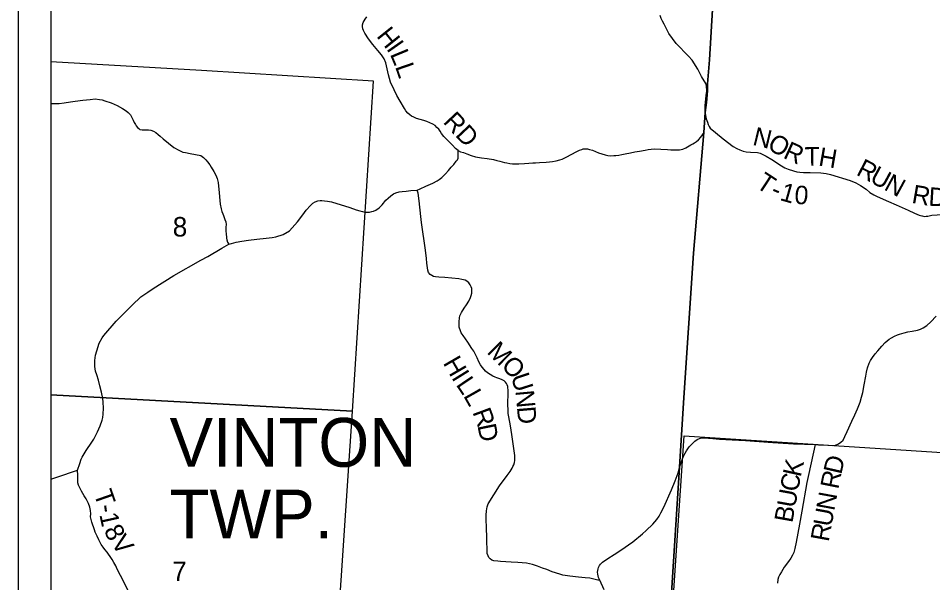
# Model space of a CAD drawing. Extents: x 0 to 34, y 0 to 22.
# Drawn here: x 2 to 4.807, y 15.408 to 17.141 of the extents above; entities that cross this region are included whole.
import ezdxf

# ---------------------------------------------------------------- set-up
doc = ezdxf.new("R2010")
doc.units = 0
for name, color, linetype in [('GM_X_Corporation', 7, 'Continuous'), ('GM_X_County_Road', 7, 'Continuous'), ('GM_X_County_Road_Text', 7, 'Continuous'), ('GM_X_Section_Text', 7, 'Continuous'), ('GM_X_State_Route', 7, 'Continuous'), ('GM_X_Township_Road', 7, 'Continuous'), ('GM_X_Township_Road_Text', 7, 'Continuous'), ('GM_X_Township_Text', 7, 'Continuous'), ('SH_Data', 7, 'Continuous')]:
    doc.layers.add(name, color=color, linetype=linetype)

msp = doc.modelspace()

# ---------------------------------------------------------------- linework, layer by layer
at = {"layer": 'GM_X_Corporation'}
msp.add_lwpolyline([(2.1, 20.9), (2.1, 14.9497), (2.4519, 14.9275), (2.9562, 14.8958), (3.5107, 14.8614), (3.9742, 14.8327), (4.0069, 15.4088), (4.03, 15.7625), (4.0425, 15.9604), (4.0732, 16.4197), (4.1048, 16.7908), (4.1087, 16.8515), (4.1128, 16.8828), (4.1159, 16.9184), (4.1162, 16.9397), (4.1215, 17.0136), (4.1603, 17.6679)], dxfattribs=at)
for points in [[(2.1, 17.0076), (2.1, 15.9854), (3.0263, 15.9353), (3.0901, 16.9477), (2.5628, 16.9805)], [(2.1, 15.9854), (2.1, 14.9539), (2.9567, 14.8961), (3.0263, 15.9353)], [(4.0444, 15.8589), (5.0732, 15.7926), (5.0032, 14.775), (3.9752, 14.8336)]]:
    msp.add_lwpolyline(points, close=True, dxfattribs=at)
at = {"layer": 'GM_X_County_Road'}
for points in [[(3.3504, 16.7349), (3.3423, 16.7416), (3.3334, 16.7517), (3.3249, 16.7602), (3.3162, 16.7682), (3.3067, 16.7779), (3.2993, 16.7874), (3.2947, 16.7941), (3.2906, 16.8005), (3.2852, 16.8061), (3.2793, 16.8119), (3.2721, 16.8164), (3.2634, 16.8206), (3.2541, 16.824), (3.2448, 16.827), (3.2334, 16.8304), (3.2224, 16.8336), (3.2143, 16.8371), (3.2075, 16.8403), (3.2017, 16.8447), (3.1962, 16.8501), (3.1901, 16.8574), (3.1858, 16.8636), (3.1725, 16.8871), (3.162, 16.9037), (3.1535, 16.9214), (3.1431, 16.9451), (3.1393, 16.9565), (3.1361, 16.9679), (3.1283, 17.0047), (3.123, 17.0169), (3.1152, 17.0285), (3.1042, 17.0418), (3.0887, 17.0602), (3.0752, 17.0782), (3.0639, 17.0953), (3.0597, 17.1031), (3.0577, 17.1087), (3.0566, 17.1156), (3.0568, 17.1206), (3.0588, 17.1282), (3.0646, 17.1383), (3.0699, 17.1452)], [(3.3504, 16.7349), (3.3574, 16.7315), (3.3666, 16.7287), (3.3769, 16.7251), (3.3905, 16.7197), (3.4039, 16.7158), (3.422, 16.713), (3.4392, 16.7107), (3.4584, 16.7073), (3.4687, 16.7047), (3.4783, 16.7021), (3.4924, 16.6985), (3.4999, 16.6968), (3.5094, 16.6952), (3.5174, 16.6944), (3.5238, 16.6942), (3.5364, 16.6945), (3.5538, 16.6953), (3.5675, 16.6963), (3.5793, 16.6971), (3.5875, 16.6975), (3.6004, 16.6985), (3.6204, 16.6998), (3.6302, 16.7004), (3.6403, 16.7016), (3.6516, 16.703), (3.662, 16.7063), (3.6692, 16.7085), (3.6817, 16.7142), (3.7148, 16.7318), (3.7226, 16.7358), (3.7295, 16.7387), (3.7344, 16.7407), (3.741, 16.7407), (3.7473, 16.7402), (3.7539, 16.7385), (3.7629, 16.7359), (3.7719, 16.7322), (3.7815, 16.7279), (3.7915, 16.7245), (3.8017, 16.7217), (3.81, 16.7202), (3.8177, 16.7189), (3.8282, 16.7193), (3.8343, 16.7195), (3.8432, 16.7212), (3.8526, 16.7228), (3.8629, 16.7251), (3.8796, 16.7281), (3.8931, 16.7313), (3.9067, 16.7336), (3.9241, 16.7366), (3.9337, 16.7384), (3.943, 16.7392), (3.952, 16.7399), (3.9926, 16.7379), (4.0029, 16.7372), (4.0183, 16.7369), (4.0293, 16.7371), (4.0347, 16.7382), (4.0398, 16.7392), (4.0495, 16.7431), (4.0643, 16.7521), (4.0705, 16.7557), (4.0756, 16.7585), (4.0815, 16.7627), (4.0879, 16.7683), (4.0955, 16.7765), (4.105, 16.7902)], [(3.2244, 16.6135), (3.2339, 16.6179), (3.2512, 16.6256), (3.2726, 16.6351), (3.2859, 16.6422), (3.292, 16.6465), (3.2998, 16.6526), (3.3113, 16.6634), (3.3206, 16.6734), (3.3289, 16.6841), (3.3366, 16.6926), (3.3446, 16.7021), (3.3484, 16.7068), (3.3504, 16.712), (3.3504, 16.7181), (3.3504, 16.7265), (3.3504, 16.7349)], [(2.1, 15.7257), (2.1181, 15.732), (2.1822, 15.7536), (2.1886, 15.7738), (2.1931, 15.7871), (2.196, 15.7933), (2.208, 15.8143), (2.2261, 15.8399), (2.2318, 15.8486), (2.2402, 15.8649), (2.2436, 15.8719), (2.251, 15.8897), (2.2572, 15.907), (2.2591, 15.9152), (2.261, 15.926), (2.2617, 15.9443), (2.261, 15.9624), (2.2599, 15.9741), (2.2557, 15.9935), (2.2508, 16.0124), (2.2459, 16.0304), (2.2407, 16.0466), (2.2374, 16.0575), (2.2346, 16.0718), (2.2346, 16.0907), (2.2374, 16.1067), (2.2407, 16.1202), (2.2483, 16.1434), (2.2572, 16.1598), (2.2622, 16.1674), (2.3002, 16.2112), (2.3496, 16.2605), (2.3765, 16.2857), (2.3978, 16.3001), (2.4145, 16.3115), (2.4779, 16.3511), (2.5604, 16.3982), (2.5819, 16.4097), (2.6246, 16.4349), (2.6461, 16.4473), (2.6546, 16.4497), (2.6687, 16.4536), (2.6858, 16.4564), (2.7071, 16.4597), (2.7325, 16.4627), (2.761, 16.466), (2.7795, 16.4681), (2.7908, 16.4701), (2.8129, 16.4768), (2.8328, 16.4885), (2.8567, 16.5161), (2.8733, 16.5379), (2.8842, 16.5516), (2.8968, 16.5661), (2.9045, 16.5731), (2.9115, 16.5774), (2.9191, 16.5809), (2.9267, 16.5817), (2.9323, 16.5817), (2.9405, 16.5811), (2.949, 16.5798), (2.9611, 16.5778), (3.0179, 16.5598), (3.0368, 16.5529), (3.048, 16.5499), (3.0571, 16.5475), (3.0637, 16.546), (3.0706, 16.5455), (3.0784, 16.5462), (3.0851, 16.5475), (3.0904, 16.549), (3.0975, 16.5516), (3.1083, 16.5592), (3.117, 16.5687), (3.1285, 16.5822), (3.1358, 16.5887), (3.1439, 16.5962), (3.1514, 16.6019), (3.1588, 16.6056), (3.1692, 16.6084), (3.1783, 16.6097), (3.1905, 16.6106), (3.2052, 16.6119), (3.2244, 16.6135)], [(3.7855, 15.4156), (3.7791, 15.4155), (3.7671, 15.4188), (3.7547, 15.4221), (3.7405, 15.4236), (3.72, 15.4257), (3.6933, 15.4283), (3.6717, 15.4316), (3.6621, 15.4342), (3.6392, 15.4416), (3.6225, 15.4483), (3.6091, 15.4529), (3.5942, 15.4589), (3.578, 15.4642), (3.5596, 15.4683), (3.5336, 15.4704), (3.5127, 15.4712), (3.4804, 15.4733), (3.4716, 15.4741), (3.4603, 15.4758), (3.4538, 15.4773), (3.4485, 15.4817), (3.4443, 15.4861), (3.442, 15.4907), (3.4397, 15.4982), (3.4387, 15.5475), (3.4377, 15.5764), (3.4366, 15.6031), (3.4366, 15.616), (3.4369, 15.6284), (3.4391, 15.6412), (3.442, 15.6499), (3.4775, 15.7057), (3.5003, 15.7369), (3.5097, 15.7495), (3.5165, 15.7599), (3.5186, 15.7646), (3.521, 15.7705), (3.5232, 15.7774), (3.5243, 15.7834), (3.5246, 15.7926), (3.524, 15.7988), (3.5151, 15.8636), (3.5107, 15.8896), (3.506, 15.9178), (3.5043, 15.9274), (3.5034, 15.9362), (3.503, 15.9577), (3.5037, 15.9904), (3.5035, 16.0006), (3.5032, 16.006), (3.5024, 16.0102), (3.5011, 16.0156), (3.4986, 16.0199), (3.4955, 16.0244), (3.4914, 16.0284), (3.4858, 16.0315), (3.4782, 16.0346), (3.4695, 16.0375), (3.4641, 16.0395), (3.4572, 16.0424), (3.4482, 16.0472), (3.4404, 16.0523), (3.4346, 16.0573), (3.4299, 16.0624), (3.4235, 16.0701), (3.4189, 16.077), (3.4137, 16.0866), (3.4083, 16.0984), (3.4024, 16.1108), (3.398, 16.119), (3.3927, 16.127), (3.3795, 16.1467), (3.3654, 16.1671), (3.36, 16.1751), (3.3576, 16.1817), (3.3538, 16.193), (3.353, 16.201), (3.3529, 16.2093), (3.354, 16.2218), (3.3559, 16.2275), (3.3605, 16.2377), (3.3687, 16.2512), (3.3761, 16.2611), (3.3828, 16.2728), (3.3882, 16.2841), (3.3905, 16.2904), (3.3921, 16.2972), (3.3926, 16.3041), (3.3918, 16.3111), (3.39, 16.317), (3.3875, 16.3232), (3.3831, 16.3291), (3.3774, 16.3337), (3.3715, 16.337), (3.3617, 16.3393), (3.3523, 16.3408), (3.3095, 16.3448), (3.2913, 16.3462), (3.2808, 16.3471), (3.2749, 16.3479), (3.2692, 16.3509), (3.2645, 16.3547), (3.2595, 16.361), (3.2573, 16.3681), (3.2541, 16.3892), (3.2533, 16.4031), (3.2504, 16.4289), (3.2379, 16.5145), (3.236, 16.5324), (3.2307, 16.5803), (3.2275, 16.6045), (3.2244, 16.6135)]]:
    msp.add_lwpolyline(points, dxfattribs=at)
at = {"layer": 'GM_X_State_Route'}
for points in [[(4.0302, 15.7619), (4.0387, 15.789), (4.0426, 15.799), (4.0509, 15.8132), (4.0599, 15.8251), (4.0684, 15.835), (4.0765, 15.8426), (4.0837, 15.8482), (4.0909, 15.8511), (4.0981, 15.8527), (4.1064, 15.8532), (4.1188, 15.8518), (4.1316, 15.8509), (4.1527, 15.8491), (4.1918, 15.8469), (4.2325, 15.8444), (4.316, 15.8388), (4.3794, 15.835), (4.4463, 15.8326), (4.4562, 15.8318), (4.4856, 15.83), (4.4994, 15.8296), (4.509, 15.8307), (4.5183, 15.8341), (4.5254, 15.8392), (4.5317, 15.8458), (4.5376, 15.8566), (4.5445, 15.872), (4.5591, 15.9043), (4.5684, 15.9236), (4.5765, 15.9418), (4.5844, 15.9629), (4.5889, 15.9779), (4.5926, 15.9924), (4.5968, 16.0157), (4.6019, 16.0427), (4.6043, 16.0543), (4.6072, 16.0678), (4.6123, 16.0825), (4.6157, 16.09), (4.6222, 16.0999), (4.6307, 16.1111), (4.6388, 16.1206), (4.651, 16.1344), (4.6606, 16.1452), (4.6672, 16.151), (4.6733, 16.1561), (4.6802, 16.1604), (4.6895, 16.1651), (4.6989, 16.1689), (4.705, 16.1711), (4.7198, 16.175), (4.7308, 16.178), (4.7442, 16.1805), (4.7602, 16.1839), (4.7693, 16.1868), (4.7778, 16.191), (4.7888, 16.1981), (4.801, 16.2093), (4.8174, 16.2261)], [(3.7855, 15.4156), (3.7813, 15.4245), (3.7787, 15.4342), (3.7785, 15.4405), (3.7786, 15.4454), (3.7796, 15.4505), (3.781, 15.4546), (3.7843, 15.4608), (3.7873, 15.4648), (3.7937, 15.4712), (3.8099, 15.4821), (3.8293, 15.4944), (3.85, 15.5086), (3.887, 15.5342), (3.9163, 15.5587), (3.9276, 15.5687), (3.9478, 15.5881), (3.954, 15.5952), (3.9599, 15.6018), (3.9671, 15.6125), (3.9727, 15.6231), (3.9816, 15.6402), (4.0052, 15.6936), (4.0166, 15.7208), (4.0253, 15.7452), (4.0302, 15.7619)], [(3.799, 15.3863), (3.7855, 15.4156)]]:
    msp.add_lwpolyline(points, dxfattribs=at)
at = {"layer": 'GM_X_Township_Road'}
for points in [[(4.1089, 16.851), (4.1083, 16.8656), (4.1083, 16.8744), (4.1093, 16.8829), (4.1119, 16.9043), (4.114, 16.9169), (4.1126, 16.9341), (4.1103, 16.9408), (4.0977, 16.9619), (4.0858, 16.9849), (4.069, 17.0126), (4.0569, 17.0251), (4.0196, 17.0634), (3.9973, 17.0947), (3.9827, 17.1231), (3.9779, 17.1325), (3.9735, 17.1409), (3.97, 17.1499)], [(2.1, 16.8798), (2.1022, 16.8795), (2.1143, 16.879), (2.1257, 16.8799), (2.1407, 16.8815), (2.1606, 16.8846), (2.1749, 16.8866), (2.1984, 16.8896), (2.2206, 16.8922), (2.2364, 16.8934), (2.2496, 16.892), (2.257, 16.8906), (2.2658, 16.8878), (2.2855, 16.8813), (2.3036, 16.8732), (2.3194, 16.8643), (2.3309, 16.8571), (2.3373, 16.8515), (2.3441, 16.8443), (2.3463, 16.8405), (2.3485, 16.8365), (2.3526, 16.8282), (2.3561, 16.8211), (2.3595, 16.8146), (2.362, 16.8104), (2.366, 16.8057), (2.3696, 16.8029), (2.3734, 16.8001), (2.3799, 16.7985), (2.3866, 16.7987), (2.393, 16.7983), (2.3993, 16.7985), (2.4072, 16.7978), (2.4154, 16.7947), (2.4224, 16.7902), (2.4289, 16.7844), (2.4356, 16.7788), (2.4447, 16.7714), (2.4776, 16.7446), (2.493, 16.7358), (2.5047, 16.7302), (2.5128, 16.7291), (2.5273, 16.7255), (2.5599, 16.7202), (2.5685, 16.7141), (2.5756, 16.707), (2.581, 16.7001), (2.5877, 16.6913), (2.5924, 16.684), (2.6007, 16.6703), (2.6063, 16.6595), (2.6105, 16.6488), (2.6139, 16.6365), (2.615, 16.6256), (2.6161, 16.6166), (2.6168, 16.605), (2.6185, 16.5819), (2.6199, 16.5708), (2.6224, 16.556), (2.6246, 16.5475), (2.6277, 16.5406), (2.6302, 16.5354), (2.6342, 16.5238), (2.6373, 16.5164), (2.6378, 16.5081), (2.6376, 16.5), (2.6376, 16.4886), (2.638, 16.4779), (2.6387, 16.4694), (2.6391, 16.4656), (2.6398, 16.4611), (2.642, 16.4539), (2.6461, 16.4473)], [(4.1089, 16.851), (4.1099, 16.8425), (4.1121, 16.8325), (4.1155, 16.8224), (4.1178, 16.8147), (4.1204, 16.8086), (4.124, 16.8041), (4.1402, 16.7904), (4.1635, 16.7713), (4.1946, 16.7478), (4.2053, 16.741), (4.2148, 16.7367), (4.2247, 16.7335), (4.2349, 16.7312), (4.2472, 16.7303), (4.2688, 16.729), (4.2775, 16.7265), (4.2859, 16.7229), (4.2963, 16.7173), (4.3131, 16.7073), (4.3425, 16.6879), (4.3528, 16.6824), (4.3637, 16.6775), (4.3796, 16.6723), (4.3899, 16.6698), (4.3991, 16.6685), (4.4103, 16.6678), (4.4306, 16.6678), (4.4637, 16.6664), (4.4796, 16.6642), (4.4932, 16.6611), (4.5536, 16.6433), (4.5713, 16.6361), (4.585, 16.628), (4.6024, 16.6161), (4.6144, 16.6067), (4.6267, 16.5992), (4.6364, 16.5937), (4.6711, 16.5789), (4.6945, 16.5687), (4.7316, 16.5523), (4.7511, 16.5429), (4.7587, 16.5395), (4.7655, 16.537), (4.7741, 16.5345)], [(4.7741, 16.5345), (4.7751, 16.5342), (4.7815, 16.5329), (4.7867, 16.5331), (4.7916, 16.534), (4.8041, 16.5363), (4.8204, 16.5378), (4.844, 16.5399), (4.8608, 16.5408), (4.8834, 16.5431), (4.9095, 16.5435), (4.9265, 16.5431)], [(4.4463, 15.8326), (4.4264, 15.743), (4.4211, 15.7159), (4.4055, 15.6277), (4.3984, 15.5883), (4.3878, 15.5329), (4.3836, 15.5128), (4.3803, 15.5011), (4.3769, 15.4925), (4.3718, 15.4836), (4.3641, 15.4731), (4.3515, 15.4558), (4.3432, 15.4416), (4.3381, 15.4333), (4.334, 15.4248), (4.3314, 15.4177), (4.3309, 15.4073)], [(2.3387, 15.3827), (2.314, 15.4304), (2.3034, 15.45), (2.299, 15.4598), (2.2937, 15.4707), (2.2884, 15.4793), (2.2825, 15.4885), (2.2773, 15.4957), (2.2726, 15.5021), (2.2657, 15.51), (2.2601, 15.5176), (2.2549, 15.5253), (2.2474, 15.5394), (2.2417, 15.5506), (2.2362, 15.563), (2.2341, 15.5701), (2.2256, 15.594), (2.2233, 15.602), (2.2221, 15.6104), (2.2226, 15.6201), (2.2221, 15.6294), (2.2201, 15.6402), (2.2155, 15.6512), (2.2079, 15.6659), (2.2022, 15.6753), (2.1941, 15.6891), (2.1887, 15.6992), (2.185, 15.7073), (2.1832, 15.7145), (2.1829, 15.7236), (2.1826, 15.7386), (2.1822, 15.7536)]]:
    msp.add_lwpolyline(points, dxfattribs=at)
at = {"layer": 'GM_X_Township_Text'}
msp.add_lwpolyline([(4.1603, 17.6679), (4.1215, 17.0136), (4.1162, 16.9397), (4.1159, 16.9184), (4.1128, 16.8828), (4.1087, 16.8515), (4.1048, 16.7908), (4.0732, 16.4197), (4.0425, 15.9604), (4.03, 15.7625), (4.0069, 15.4088), (3.9742, 14.8327), (3.9197, 14.1)], dxfattribs=at)
at = {"layer": 'SH_Data'}
for p, q in [((2, 21), (2, 14)), ((2.1, 20.9), (2.1, 14.1))]:
    msp.add_line(p, q, dxfattribs=at)

# ---------------------------------------------------------------- texts
at = {"layer": 'GM_X_County_Road_Text'}
for s, height, rotation, p in [('H', 0.0568, 308.7281, (3.0977, 17.0859)), ('I', 0.0568, 305.0195, (3.1284, 17.0476)), ('L', 0.0568, 292.4524, (3.1402, 17.0314)), ('L', 0.0568, 289.0692, (3.1561, 16.993)), ('RD', 0.05682, 313.2412, (3.3016, 16.8213)), ('M', 0.0568, 315.3216, (3.436, 16.1144)), ('H', 0.0568, 300.091, (3.3024, 16.083)), ('O', 0.0568, 314.7321, (3.4798, 16.0712)), ('I', 0.0568, 301.9123, (3.3284, 16.0381)), ('L', 0.0568, 303.884, (3.3419, 16.0165)), ('U', 0.0568, 288.0214, (3.5114, 16.0416)), ('L', 0.0568, 299.6311, (3.365, 15.9822)), ('N', 0.0568, 275.1067, (3.5262, 15.9973)), ('R', 0.0568, 290.3546, (3.3935, 15.9322)), ('D', 0.0568, 274.8946, (3.5306, 15.9476)), ('D', 0.0568, 281.4635, (3.4091, 15.8907))]:
    msp.add_text(s, height=height, rotation=rotation, dxfattribs=at).set_placement(p)
at = {"layer": 'GM_X_Section_Text'}
for s, p in [('8', (2.4741, 16.471)), ('7', (2.4724, 15.4132))]:
    msp.add_text(s, height=0.06, rotation=0, dxfattribs=at).set_placement(p)
at = {"layer": 'GM_X_Township_Road_Text'}
for s, rotation, p in [('N', 346.2968, (4.2515, 16.7529)), ('O', 328.692, (4.2958, 16.7428)), ('R', 335.4952, (4.3451, 16.7134)), ('T', 1.0712, (4.4144, 16.6885)), ('H', 350.2155, (4.4541, 16.6895)), ('R', 332.5456, (4.5693, 16.6616)), ('U', 331.5506, (4.6105, 16.6402)), ('T', 326.5465, (4.2611, 16.6241)), ('N', 331.5335, (4.6545, 16.6164)), ('1', 344.1031, (4.3351, 16.5835)), ('0', 355.8261, (4.3812, 16.5717)), ('R', 350.1392, (4.7404, 16.5747)), ('D', 356.404, (4.793, 16.5659)), ('-', 336.4229, (4.3059, 16.5956)), ('K', 77.6674, (4.4017, 15.7304)), ('D', 77.0638, (4.5262, 15.7384)), ('R', 78.638, (4.5171, 15.6931)), ('C', 79.5347, (4.3933, 15.685)), ('T', 289.3966, (2.231, 15.6823)), ('U', 79.7478, (4.3844, 15.6359)), ('N', 79.5231, (4.5048, 15.627)), ('-', 278.1034, (2.2444, 15.6452)), ('B', 79.7491, (4.3761, 15.59)), ('U', 79.716, (4.4959, 15.5778)), ('1', 282.4646, (2.2485, 15.6177)), ('8', 296.9379, (2.2613, 15.5691)), ('R', 79.7388, (4.4875, 15.5319)), ('V', 306.3207, (2.2823, 15.5295))]:
    msp.add_text(s, height=0.0568, rotation=rotation, dxfattribs=at).set_placement(p)
at = {"layer": 'GM_X_Township_Text'}
for s, p in [('VINTON', (2.4643, 15.7641)), ('TWP.', (2.4643, 15.5441))]:
    msp.add_text(s, height=0.15, rotation=0, dxfattribs=at).set_placement(p)

doc.saveas('drawing.dxf')
